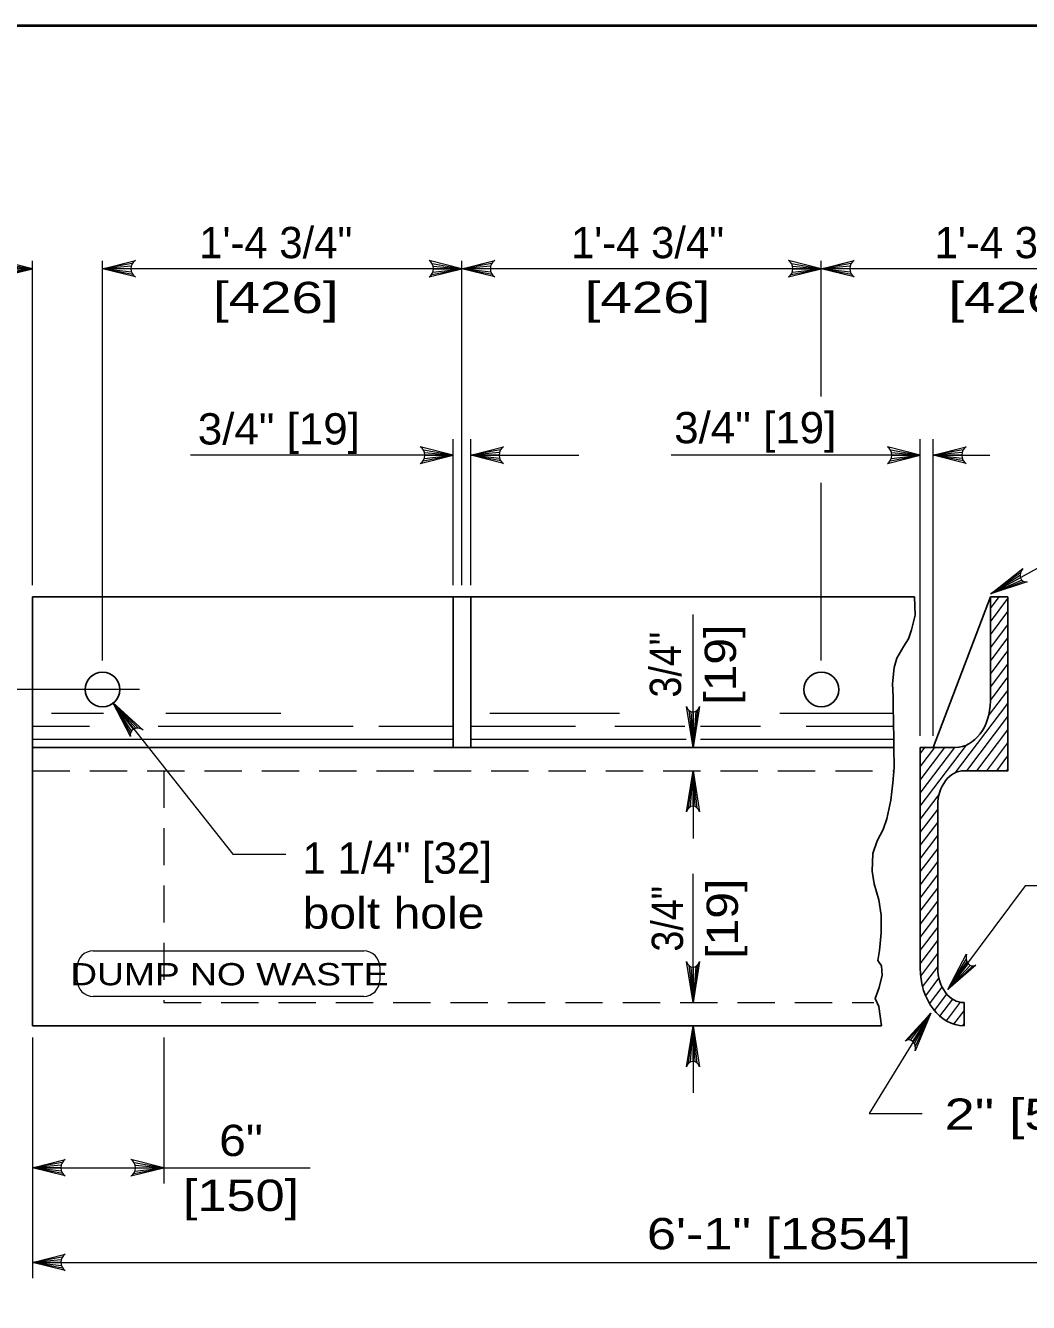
# Model space of a CAD drawing. Extents: x 1352.5 to 1386.5, y 735.9 to 779.9.
# Drawn here: x 1356.98 to 1361.98, y 751.05 to 757.42 of the extents above; entities that cross this region are included whole.
import ezdxf
from ezdxf.enums import TextEntityAlignment as Align

# ---------------------------------------------------------------- set-up
doc = ezdxf.new("R2010")
doc.units = 0
doc.header["$LTSCALE"] = 0.062
doc.linetypes.add('MEDIUM_DASHED', pattern=[4.5, 3, -1.5])
doc.layers.add('1', color=7, linetype='Continuous', lineweight=13)

msp = doc.modelspace()

# ---------------------------------------------------------------- linework, layer by layer
at = {"layer": '1', "lineweight": 25}
for p, q in [((1354.513, 757.41967), (1386.013, 757.41967)), ((1357.017, 754.56975), (1357.017, 752.42942)), ((1361.41508, 754.56975), (1357.017, 754.56975)), ((1359.11517, 754.56975), (1359.11517, 754.50958)), ((1359.20258, 754.56975), (1359.20258, 754.50958)), ((1361.79383, 754.56975), (1361.5095, 753.81775)), ((1361.79383, 754.04917), (1361.79383, 754.56975)), ((1361.79383, 754.56975), (1361.88125, 754.56975)), ((1359.11517, 754.50958), (1359.11517, 753.81775)), ((1359.20258, 754.50958), (1359.20258, 753.81775)), ((1357.017, 753.81775), (1361.313, 753.81775)), ((1361.875, 753.70208), (1361.88125, 753.71025)), ((1361.53158, 753.5285), (1361.53158, 752.71867)), ((1361.66275, 752.54508), (1361.66275, 752.42942)), ((1357.017, 752.42942), (1361.25075, 752.42942))]:
    msp.add_line(p, q, dxfattribs=at)
at = {"layer": '1'}
for p, q in [((1357.017, 754.62758), (1357.017, 756.24592)), ((1357.36675, 754.25158), (1357.36675, 756.24592)), ((1359.15892, 754.62758), (1359.15892, 756.24592)), ((1360.95108, 755.569), (1360.95108, 756.24592)), ((1357.017, 756.20658), (1356.26483, 756.20658)), ((1356.86683, 756.17792), (1357.017, 756.20658)), ((1356.86858, 756.23258), (1357.017, 756.20658)), ((1356.87258, 756.18992), (1357.017, 756.20658)), ((1356.87367, 756.21975), (1357.017, 756.20658)), ((1356.87517, 756.20658), (1357.017, 756.20658)), ((1357.51508, 756.23258), (1357.36675, 756.20658)), ((1357.51008, 756.21975), (1357.36675, 756.20658)), ((1357.50858, 756.20658), (1357.36675, 756.20658)), ((1357.51117, 756.18992), (1357.36675, 756.20658)), ((1357.51683, 756.17792), (1357.36675, 756.20658)), ((1361.41508, 756.20658), (1357.36675, 756.20658)), ((1364.5355, 756.20658), (1357.36675, 756.20658)), ((1359.00875, 756.17792), (1359.15892, 756.20658)), ((1359.0105, 756.23258), (1359.15892, 756.20658)), ((1359.01442, 756.18992), (1359.15892, 756.20658)), ((1359.0155, 756.21975), (1359.15892, 756.20658)), ((1359.01708, 756.20658), (1359.15892, 756.20658)), ((1359.30733, 756.23258), (1359.15892, 756.20658)), ((1359.30225, 756.21975), (1359.15892, 756.20658)), ((1359.30075, 756.20658), (1359.15892, 756.20658)), ((1359.30333, 756.18992), (1359.15892, 756.20658)), ((1359.30908, 756.17792), (1359.15892, 756.20658)), ((1360.80092, 756.17792), (1360.95108, 756.20658)), ((1360.80267, 756.23258), (1360.95108, 756.20658)), ((1360.80667, 756.18992), (1360.95108, 756.20658)), ((1360.80775, 756.21975), (1360.95108, 756.20658)), ((1360.80925, 756.20658), (1360.95108, 756.20658)), ((1361.0995, 756.23258), (1360.95108, 756.20658)), ((1361.0945, 756.21975), (1360.95108, 756.20658)), ((1361.09292, 756.20658), (1360.95108, 756.20658)), ((1361.09558, 756.18992), (1360.95108, 756.20658)), ((1361.10125, 756.17792), (1360.95108, 756.20658)), ((1359.11517, 754.62758), (1359.11517, 755.35642)), ((1359.20258, 754.62758), (1359.20258, 755.35642)), ((1361.44417, 753.87558), (1361.44417, 755.35642)), ((1361.5095, 753.87558), (1361.5095, 755.35642)), ((1358.96675, 755.30225), (1359.11517, 755.27625)), ((1358.97183, 755.28942), (1359.11517, 755.27625)), ((1359.351, 755.30225), (1359.20258, 755.27625)), ((1359.346, 755.28942), (1359.20258, 755.27625)), ((1361.29575, 755.30225), (1361.44417, 755.27625)), ((1361.30075, 755.28942), (1361.44417, 755.27625)), ((1361.65792, 755.30225), (1361.5095, 755.27625)), ((1361.65292, 755.28942), (1361.5095, 755.27625)), ((1359.11517, 755.27625), (1357.80483, 755.27625)), ((1358.965, 755.24758), (1359.11517, 755.27625)), ((1358.97075, 755.25958), (1359.11517, 755.27625)), ((1358.97333, 755.27625), (1359.11517, 755.27625)), ((1359.20258, 755.27625), (1359.74183, 755.27625)), ((1359.3445, 755.27625), (1359.20258, 755.27625)), ((1359.34708, 755.25958), (1359.20258, 755.27625)), ((1359.35275, 755.24758), (1359.20258, 755.27625)), ((1361.44417, 755.27625), (1360.2025, 755.27625)), ((1361.294, 755.24758), (1361.44417, 755.27625)), ((1361.29967, 755.25958), (1361.44417, 755.27625)), ((1361.30233, 755.27625), (1361.44417, 755.27625)), ((1361.5095, 755.27625), (1361.79125, 755.27625)), ((1361.65133, 755.27625), (1361.5095, 755.27625)), ((1361.654, 755.25958), (1361.5095, 755.27625)), ((1361.65967, 755.24758), (1361.5095, 755.27625)), ((1360.95108, 755.05), (1360.95108, 755.1375)), ((1360.95108, 754.25158), (1360.95108, 755.05292)), ((1361.94392, 754.68992), (1361.79592, 754.58492)), ((1361.94192, 754.67658), (1361.79592, 754.58492)), ((1361.94367, 754.66483), (1361.79592, 754.58492)), ((1361.95058, 754.65258), (1361.79592, 754.58492)), ((1361.9595, 754.64592), (1361.79592, 754.58492)), ((1361.79383, 754.51083), (1361.83833, 754.56975)), ((1361.79383, 754.44542), (1361.88125, 754.56108)), ((1360.31133, 753.81775), (1360.31133, 754.48142)), ((1361.79383, 754.37992), (1361.88125, 754.49567)), ((1361.79383, 754.3145), (1361.88125, 754.43017)), ((1361.79383, 754.249), (1361.88125, 754.36467)), ((1361.79383, 754.18367), (1361.88125, 754.29933)), ((1361.79383, 754.11817), (1361.88125, 754.23383)), ((1361.79383, 754.05267), (1361.88125, 754.16842)), ((1357.25742, 754.107), (1356.26967, 754.107)), ((1357.55133, 754.107), (1356.56358, 754.107)), ((1361.78467, 753.97508), (1361.88125, 754.10292)), ((1357.41775, 754.04258), (1358.01717, 753.28533)), ((1357.52175, 753.90992), (1357.41775, 754.04258)), ((1357.51092, 753.901), (1357.41775, 754.04258)), ((1357.50583, 753.891), (1357.41775, 754.04258)), ((1357.53283, 753.91358), (1357.41775, 754.04258)), ((1357.54642, 753.91383), (1357.41775, 754.04258)), ((1361.62083, 753.69292), (1361.88125, 754.0375)), ((1357.113, 753.98942), (1357.37175, 753.98942)), ((1357.68208, 753.98942), (1358.25525, 753.98942)), ((1359.29817, 753.98942), (1359.94458, 753.98942)), ((1360.2905, 754.00325), (1360.31133, 753.81775)), ((1360.30083, 753.997), (1360.31133, 753.81775)), ((1360.33425, 754.00542), (1360.31133, 753.81775)), ((1360.32458, 753.99833), (1360.31133, 753.81775)), ((1360.31133, 753.99508), (1360.31133, 753.81775)), ((1360.74475, 753.98942), (1361.30933, 753.98942)), ((1361.67725, 753.70208), (1361.88125, 753.972)), ((1357.017, 753.92408), (1357.3015, 753.92408)), ((1357.64483, 753.92408), (1358.61725, 753.92408)), ((1358.74425, 753.92408), (1359.11517, 753.92408)), ((1359.20258, 753.92408), (1359.72525, 753.92408)), ((1359.92142, 753.92408), (1360.27033, 753.92408)), ((1360.34908, 753.92408), (1360.64858, 753.92408)), ((1360.87558, 753.92408), (1361.31117, 753.92408)), ((1361.72667, 753.70208), (1361.88125, 753.90667)), ((1357.017, 753.85875), (1359.11517, 753.85875)), ((1359.20258, 753.85875), (1360.27667, 753.85875)), ((1360.34908, 753.85875), (1361.3125, 753.85875)), ((1361.44417, 753.52458), (1361.67492, 753.82983)), ((1361.44417, 753.58992), (1361.61633, 753.81775)), ((1361.44417, 753.65542), (1361.56683, 753.81775)), ((1361.44417, 753.72083), (1361.51742, 753.81775)), ((1361.44417, 753.78633), (1361.46792, 753.81775)), ((1361.77608, 753.70208), (1361.88125, 753.84117)), ((1361.82558, 753.70208), (1361.88125, 753.77567)), ((1360.28833, 753.51433), (1360.31133, 753.70208)), ((1360.298, 753.5215), (1360.31133, 753.70208)), ((1360.31133, 753.52475), (1360.31133, 753.70208)), ((1360.32175, 753.52283), (1360.31133, 753.70208)), ((1360.33208, 753.51658), (1360.31133, 753.70208)), ((1360.31133, 753.70208), (1360.31133, 753.36467)), ((1361.44417, 753.459), (1361.5385, 753.58392)), ((1361.44417, 753.39358), (1361.53158, 753.50933)), ((1361.44417, 753.32817), (1361.53158, 753.44383)), ((1361.44417, 753.26267), (1361.53158, 753.3785)), ((1361.44417, 753.19725), (1361.53158, 753.313)), ((1358.01717, 753.28533), (1358.281, 753.28533)), ((1361.44417, 753.13175), (1361.53158, 753.24758)), ((1360.31133, 752.54508), (1360.31133, 753.187)), ((1361.44417, 753.06642), (1361.53158, 753.18208)), ((1361.44417, 753.00092), (1361.53158, 753.11667)), ((1361.96833, 753.128), (1361.58175, 752.61)), ((1362.19833, 753.128), (1361.96833, 753.128)), ((1361.44417, 752.9355), (1361.53158, 753.05125)), ((1361.44417, 752.87), (1361.53158, 752.98575)), ((1361.44417, 752.8045), (1361.53158, 752.92033)), ((1357.32075, 752.80325), (1358.669, 752.80325)), ((1361.44417, 752.73908), (1361.53158, 752.85483)), ((1360.33425, 752.73275), (1360.31133, 752.54508)), ((1361.4465, 752.67675), (1361.53158, 752.78942)), ((1361.67267, 752.76325), (1361.58175, 752.61)), ((1361.67633, 752.74992), (1361.58175, 752.61)), ((1361.68267, 752.73958), (1361.58175, 752.61)), ((1357.24075, 752.65617), (1357.24075, 752.72325)), ((1358.749, 752.72325), (1358.749, 752.65617)), ((1360.2905, 752.73058), (1360.31133, 752.54508)), ((1360.30083, 752.72433), (1360.31133, 752.54508)), ((1360.32458, 752.72567), (1360.31133, 752.54508)), ((1360.31133, 752.72242), (1360.31133, 752.54508)), ((1361.45617, 752.62417), (1361.53158, 752.72392)), ((1361.69392, 752.73067), (1361.58175, 752.61)), ((1361.70475, 752.72767), (1361.58175, 752.61)), ((1361.4715, 752.57892), (1361.53767, 752.6665)), ((1361.49117, 752.53958), (1361.55375, 752.62233)), ((1358.669, 752.57617), (1357.32075, 752.57617)), ((1361.515, 752.50567), (1361.57692, 752.58758)), ((1361.54283, 752.477), (1361.60683, 752.56175)), ((1361.57483, 752.454), (1361.645, 752.54683)), ((1361.38467, 752.35917), (1361.49675, 752.49325)), ((1361.39575, 752.35775), (1361.49675, 752.49325)), ((1361.40783, 752.35058), (1361.49675, 752.49325)), ((1361.41508, 752.34125), (1361.49675, 752.49325)), ((1361.41992, 752.32858), (1361.49675, 752.49325)), ((1361.61183, 752.43742), (1361.66275, 752.50475)), ((1360.28833, 752.24167), (1360.31133, 752.42942)), ((1360.298, 752.24883), (1360.31133, 752.42942)), ((1360.31133, 752.42942), (1360.31133, 752.09525)), ((1360.31133, 752.25208), (1360.31133, 752.42942)), ((1360.32175, 752.25017), (1360.31133, 752.42942)), ((1360.33208, 752.24392), (1360.31133, 752.42942)), ((1361.65542, 752.42967), (1361.66275, 752.43933)), ((1357.017, 752.3715), (1357.017, 751.17075)), ((1357.67267, 752.3715), (1357.67267, 751.64275)), ((1357.16542, 751.74733), (1357.017, 751.72142)), ((1357.16042, 751.7345), (1357.017, 751.72142)), ((1357.15883, 751.72142), (1357.017, 751.72142)), ((1357.1615, 751.70475), (1357.017, 751.72142)), ((1357.16717, 751.69275), (1357.017, 751.72142)), ((1357.017, 751.72142), (1358.40283, 751.72142)), ((1357.52258, 751.69275), (1357.67267, 751.72142)), ((1357.52425, 751.74733), (1357.67267, 751.72142)), ((1357.52825, 751.70475), (1357.67267, 751.72142)), ((1357.52933, 751.7345), (1357.67267, 751.72142)), ((1357.53083, 751.72142), (1357.67267, 751.72142)), ((1357.16542, 751.27533), (1357.017, 751.24942)), ((1357.16042, 751.2625), (1357.017, 751.24942)), ((1357.15883, 751.24942), (1357.017, 751.24942)), ((1357.1615, 751.23275), (1357.017, 751.24942)), ((1357.16717, 751.22067), (1357.017, 751.24942)), ((1357.017, 751.24942), (1364.88517, 751.24942))]:
    msp.add_line(p, q, dxfattribs=at)
at = {"layer": '1', "linetype": 'MEDIUM_DASHED'}
msp.add_line((1357.017, 753.70208), (1361.31225, 753.70208), dxfattribs=at)
at = {"layer": '1', "lineweight": 40}
msp.add_lwpolyline([(1354.513, 757.41967), (1386.013, 757.41967), (1386.013, 736.41967), (1354.513, 736.41967)], close=True, dxfattribs=at)
msp.add_lwpolyline([(1354.513, 757.41967), (1386.013, 757.41967), (1386.013, 736.41967), (1354.513, 736.41967)], close=True, dxfattribs=at)
at = {"layer": '1'}
for points in [[(1356.85308, 756.16567), (1357.017, 756.20658), (1356.85308, 756.24758)], [(1357.53067, 756.16567), (1357.36675, 756.20658), (1357.53067, 756.24758)], [(1358.995, 756.16567), (1359.15892, 756.20658), (1358.995, 756.24758)], [(1359.32283, 756.16567), (1359.15892, 756.20658), (1359.32283, 756.24758)], [(1360.78717, 756.16567), (1360.95108, 756.20658), (1360.78717, 756.24758)], [(1361.115, 756.16567), (1360.95108, 756.20658), (1361.115, 756.24758)], [(1358.95125, 755.23525), (1359.11517, 755.27625), (1358.95125, 755.31725)], [(1359.3665, 755.23525), (1359.20258, 755.27625), (1359.3665, 755.31725)], [(1361.28025, 755.23525), (1361.44417, 755.27625), (1361.28025, 755.31725)], [(1361.67342, 755.23525), (1361.5095, 755.27625), (1361.67342, 755.31725)], [(1361.79592, 754.58492), (1362.44575, 754.94258), (1363.02867, 754.94258)], [(1361.97692, 754.64358), (1361.79592, 754.58492), (1361.95633, 754.71108)], [(1357.5065, 753.87342), (1357.41775, 754.04258), (1357.56925, 753.90508)], [(1360.34408, 754.02267), (1360.31133, 753.81775), (1360.2785, 754.02267)], [(1360.2785, 753.49717), (1360.31133, 753.70208), (1360.34408, 753.49717)], [(1360.34408, 752.75), (1360.31133, 752.54508), (1360.2785, 752.75)], [(1361.7215, 752.73192), (1361.58175, 752.61), (1361.67525, 752.78767)], [(1361.49675, 752.49325), (1361.19025, 751.99217), (1361.45408, 751.99217)], [(1361.36833, 752.35258), (1361.49675, 752.49325), (1361.41958, 752.30417)], [(1360.2785, 752.2245), (1360.31133, 752.42942), (1360.34408, 752.2245)], [(1357.18092, 751.68042), (1357.017, 751.72142), (1357.18092, 751.76242)], [(1357.50875, 751.68042), (1357.67267, 751.72142), (1357.50875, 751.76242)], [(1357.18092, 751.20842), (1357.017, 751.24942), (1357.18092, 751.29042)]]:
    msp.add_lwpolyline(points, dxfattribs=at)
at = {"layer": '1', "lineweight": 25}
for points in [[(1361.41508, 754.56975), (1361.41908, 754.47875), (1361.40075, 754.4045), (1361.38625, 754.36), (1361.36317, 754.3235), (1361.32758, 754.26425), (1361.31392, 754.21733), (1361.30592, 754.13517), (1361.3085, 754.07125), (1361.30858, 754.01067), (1361.3105, 753.95358), (1361.31267, 753.85192), (1361.313, 753.81775), (1361.3135, 753.71825), (1361.30725, 753.64175), (1361.29833, 753.555), (1361.278, 753.46258), (1361.25983, 753.40883), (1361.2295, 753.35183), (1361.20867, 753.289), (1361.20408, 753.20108), (1361.21458, 753.13833), (1361.237, 753.05825), (1361.24908, 752.98058), (1361.24875, 752.89267), (1361.24067, 752.80592), (1361.23225, 752.75567), (1361.251, 752.72817), (1361.25383, 752.68133), (1361.23917, 752.61975), (1361.22017, 752.56492), (1361.237, 752.526), (1361.25075, 752.42942)], [(1361.88125, 754.56975), (1361.88125, 753.70208), (1361.66275, 753.70208)], [(1361.44417, 752.71867), (1361.44417, 753.81775), (1361.619, 753.81775)]]:
    msp.add_lwpolyline(points, dxfattribs=at)
at = {"layer": '1', "linetype": 'MEDIUM_DASHED'}
msp.add_lwpolyline([(1357.67267, 753.70208), (1357.67267, 752.54508), (1361.21325, 752.54508)], dxfattribs=at)
at = {"layer": '1', "lineweight": 25}
for centre in [(1357.36671, 754.10698), (1360.95109, 754.10699)]:
    msp.add_circle(centre, 0.08677, dxfattribs=at)
at = {"layer": '1'}
for centre, start, end in [((1357.32075, 752.72325), 90, 180), ((1358.669, 752.72325), 0, 90), ((1357.32075, 752.65617), 180, 270), ((1358.669, 752.65617), 270, 0)]:
    msp.add_arc(centre, 0.08, start, end, dxfattribs=at)
for centre, major_axis, start_param, end_param in [((1357.54387, 756.20666), (0, 0.04422), 0.3855052, 2.7561184), ((1358.98174, 756.20666), (0, 0.04422), 3.5270669, 5.8976801), ((1359.33606, 756.20666), (0, 0.04422), 0.3855052, 2.7561184), ((1360.77393, 756.20666), (0, 0.04422), 3.5270669, 5.8976801), ((1361.12825, 756.20666), (0, 0.04422), 0.3855052, 2.7561184), ((1358.93803, 755.27631), (0, 0.04422), 3.5270669, 5.8976801), ((1359.37977, 755.27631), (0, 0.04422), 0.3855052, 2.7561184), ((1361.267, 755.27631), (0, 0.04422), 3.5270669, 5.8976801), ((1361.68667, 755.27631), (0, 0.04422), 0.3855052, 2.7561184), ((1361.98042, 754.68482), (0.02527, 0.03629), 1.3945655, 3.7651786), ((1360.31126, 754.03919), (0, -0.04422), 5.0978942, 7.4685073), ((1357.54764, 753.87689), (0.0397, -0.01948), 1.4132856, 3.7838987), ((1360.31133, 753.4806), (0, 0.04422), 5.0978942, 7.4685073), ((1360.31126, 752.76654), (0, -0.04422), 5.0978942, 7.4685073), ((1361.70776, 752.77193), (0.00393, 0.04405), 1.2784222, 3.6490354), ((1361.38568, 752.315), (-0.00419, -0.04403), 1.3987248, 3.769338), ((1360.31133, 752.20795), (0, 0.04422), 5.0978942, 7.4685073), ((1357.19417, 751.72144), (0, 0.04422), 0.3855052, 2.7561184), ((1357.49554, 751.72144), (0, 0.04422), 3.5270669, 5.8976801), ((1357.19417, 751.24944), (0, 0.04422), 0.3855052, 2.7561184)]:
    msp.add_ellipse(centre, major_axis=major_axis, ratio=0.8, start_param=start_param, end_param=end_param, dxfattribs=at)
at = {"layer": '1', "lineweight": 25}
for centre, major_axis, start_param, end_param in [((1361.61901, 754.04914), (0, -0.23139), 6.2831853, 7.8539816), ((1361.66272, 753.5285), (0, 0.17354), 6.2831853, 7.8539816), ((1361.66272, 752.71863), (0, -0.28924), 4.712389, 6.2831853), ((1361.66272, 752.71863), (0, -0.17354), 4.712389, 6.2831853)]:
    msp.add_ellipse(centre, major_axis=major_axis, ratio=0.755635, start_param=start_param, end_param=end_param, dxfattribs=at)

# ---------------------------------------------------------------- texts
at = {"layer": '1'}
for p in [(1358.23079, 756.259), (1360.08454, 756.259), (1361.89779, 756.259)]:
    msp.add_text('1\'-4 3/4"', height=0.156, dxfattribs=at).set_placement(p, align=Align.CENTER)
for s, width, p in [('[426]', 1.35, (1358.23079, 755.985)), ('[426]', 1.35, (1360.08454, 755.985)), ('[426]', 1.35, (1361.89779, 755.985)), ('6"', 1.15, (1358.05742, 751.77975)), ('[150]', 1.25, (1358.05742, 751.50575))]:
    msp.add_text(s, height=0.156, dxfattribs=dict(at, width=width)).set_placement(p, align=Align.CENTER)
for s, height, width, p in [('3/4" [19]', 0.156, 1.05, (1357.84183, 755.32958)), ('3/4" [19]', 0.156, 1.05, (1360.21733, 755.33567)), ('bolt hole', 0.156, 1.15, (1358.3645, 752.91417)), ('   DUMP NO WASTE   ', 0.111, 1.25, (1357.05083, 752.63142)), ('2" [50] rad.', 0.156, 1.3, (1361.56567, 751.91067)), ('6\'-1" [1854]', 0.156, 1.25, (1360.08133, 751.31467))]:
    msp.add_text(s, height=height, dxfattribs=dict(at, width=width)).set_placement(p)
for s, width, p in [('[19]', 1.15, (1360.52567, 754.23096)), ('3/4"', 0.9, (1360.25167, 754.231)), ('3/4"', 0.9, (1360.26125, 752.9635)), ('[19]', 1.15, (1360.53525, 752.96346))]:
    msp.add_text(s, height=0.156, rotation=90, dxfattribs=dict(at, width=width)).set_placement(p, align=Align.CENTER)
msp.add_text('1 1/4" [32]', height=0.156, dxfattribs=at).set_placement((1358.3645, 753.18817))

doc.saveas('drawing.dxf')
